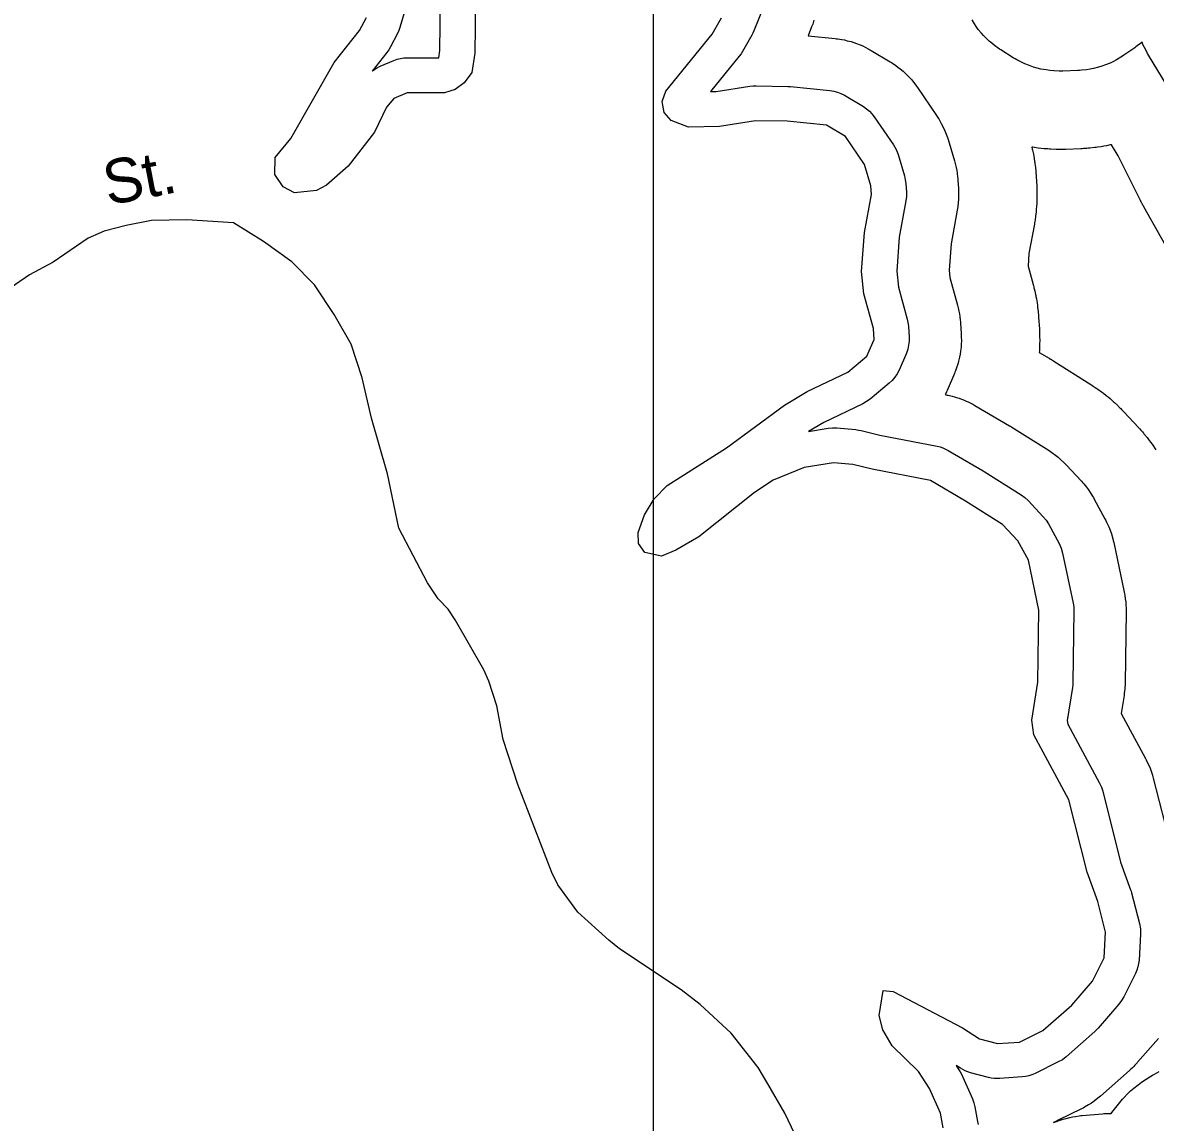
# Model space of a CAD drawing. Extents: x 1113032 to 1302912, y 664689 to 832535.
# Drawn here: x 1146316 to 1148745, y 741476 to 743835 of the extents above; entities that cross this region are included whole.
import ezdxf

# ---------------------------------------------------------------- set-up
doc = ezdxf.new("R2010")
doc.units = 0
for name, color, linetype in [('Exist Hydrographic Buffer Line', 7, 'Continuous'), ('Exist Hydrographic Lake Shore', 7, 'Continuous'), ('Exist Road Non-System Type 51', 7, 'Continuous'), ('Exist Road Non-System Type 51 Label', 7, 'Continuous'), ('Map Preparation Inset Cut Line', 7, 'Continuous')]:
    doc.layers.add(name, color=color, linetype=linetype)

msp = doc.modelspace()

# ---------------------------------------------------------------- linework, layer by layer
at = {"layer": 'Exist Hydrographic Buffer Line'}
for points in [[(1147136.6, 743863.2), (1147125.1, 743824.9), (1147122.8, 743818.4), (1147119.9, 743812), (1147105.2, 743783.7), (1147101.5, 743777.3), (1147097.2, 743771.3), (1147065.3, 743731.4), (1147067, 743732.8), (1147074.6, 743737.8), (1147082.7, 743741.8), (1147111.8, 743754), (1147118.9, 743756.6), (1147126.2, 743758.4), (1147133.7, 743759.5), (1147141.2, 743759.9), (1147208.4, 743759.6), (1147210.9, 743775.8), (1147212.4, 743886.1)], [(1147903.8, 743867.1), (1147884.3, 743817.8), (1147882.2, 743812.9), (1147879.7, 743808.2), (1147859.9, 743773.4), (1147856.6, 743768.1), (1147852.8, 743763.1), (1147791, 743687.3), (1147803.5, 743687.5), (1147875.8, 743699), (1147882.4, 743699.7), (1147889, 743699.9), (1147957, 743698.6), (1147959.9, 743698.5), (1147962.9, 743698.2), (1148047.1, 743689.8), (1148055.3, 743688.5), (1148063.2, 743686.4), (1148070.9, 743683.4), (1148078.2, 743679.5), (1148118.9, 743655.2), (1148125.6, 743650.7), (1148131.8, 743645.4), (1148137.4, 743639.6), (1148142.3, 743633.1), (1148183.3, 743573), (1148189.1, 743563.1), (1148193.2, 743552.3), (1148206.9, 743506.6), (1148208.9, 743498.4), (1148209.9, 743490.1), (1148211.2, 743471.9), (1148211.2, 743462.6), (1148210.1, 743453.3), (1148195.9, 743375.4), (1148190.4, 743302.4), (1148194.2, 743267.5), (1148212.9, 743199.4), (1148214.5, 743192), (1148215.4, 743184.4), (1148216.9, 743160.6), (1148217, 743151.8), (1148216, 743143.1), (1148214, 743134.6), (1148211.1, 743126.3), (1148195.6, 743090.1), (1148191.6, 743082.1), (1148186.7, 743074.6), (1148180.9, 743067.8), (1148174.4, 743061.7), (1148133.3, 743027.7), (1148125.9, 743022.3), (1148117.9, 743017.8), (1148034.2, 742977.8), (1148001.6, 742958.4), (1148043.3, 742965.1), (1148052.5, 742966), (1148061.9, 742965.8), (1148103, 742962.2), (1148108.6, 742961.4), (1148114.2, 742960.3), (1148154.2, 742950.5), (1148277.3, 742926.6), (1148283.5, 742925.1), (1148289.5, 742923.1), (1148295.3, 742920.6), (1148300.9, 742917.6), (1148375.7, 742873.7), (1148376.7, 742873.1), (1148377.7, 742872.5), (1148457.2, 742822.4), (1148465.1, 742816.7), (1148472.1, 742810), (1148504.8, 742775), (1148510.7, 742767.7), (1148515.7, 742759.8), (1148538.6, 742717.7), (1148543.1, 742707.8), (1148546.1, 742697.3), (1148568.7, 742590.3), (1148569.9, 742582.1), (1148570.3, 742573.8), (1148568.2, 742419.8), (1148568, 742414.5), (1148567.3, 742409.2), (1148556.3, 742338), (1148557.2, 742330.7), (1148625.4, 742203.7), (1148629.3, 742195.4), (1148632.1, 742186.6), (1148670.6, 742034.6), (1148692.1, 741975.1), (1148693.1, 741971.9), (1148694.1, 741968.6), (1148711.1, 741903.1), (1148713.2, 741891.5), (1148713.4, 741879.7), (1148710, 741824.2), (1148709.2, 741816.8), (1148707.6, 741809.5), (1148705.3, 741802.3), (1148702.3, 741795.5), (1148677.6, 741745.6), (1148672.8, 741737.3), (1148667, 741729.7), (1148622.5, 741678.5), (1148619.2, 741674.8), (1148615.6, 741671.4), (1148553.5, 741616.7), (1148545.7, 741610.6), (1148537, 741605.7), (1148487.1, 741581), (1148480.4, 741578.1), (1148473.5, 741575.9), (1148466.4, 741574.4), (1148459.2, 741573.5), (1148411.6, 741570.2), (1148405.5, 741570), (1148399.3, 741570.3), (1148393.2, 741571.2), (1148387.2, 741572.5), (1148348.7, 741582.7), (1148337.5, 741586.6), (1148327.2, 741592.2), (1148318.1, 741598), (1148323.8, 741589.1), (1148326.6, 741584.4), (1148329.1, 741579.4), (1148352.8, 741526.9), (1148356, 741518.4), (1148358.2, 741509.6), (1148363.9, 741478.3), (1148364.8, 741471.4)], [(1148012.9, 743840.5), (1148010.2, 743832.2), (1148009.1, 743829.1), (1148007.9, 743826), (1148000.4, 743807), (1148058.2, 743801.3), (1148061.3, 743800.9), (1148064.3, 743800.5), (1148072.5, 743799.2), (1148078.5, 743798.1), (1148084.5, 743796.6), (1148092.5, 743794.5), (1148098.4, 743792.7), (1148104.2, 743790.6), (1148111.8, 743787.6), (1148117.5, 743785.2), (1148123, 743782.5), (1148130.3, 743778.7), (1148133, 743777.2), (1148135.7, 743775.7), (1148176.4, 743751.3), (1148178.9, 743749.7), (1148181.5, 743748.1), (1148188.2, 743743.5), (1148193.1, 743740), (1148197.9, 743736.2), (1148204.1, 743731), (1148208.6, 743727), (1148212.9, 743722.7), (1148218.5, 743716.8), (1148222.5, 743712.3), (1148226.3, 743707.6), (1148231.3, 743701.2), (1148233.1, 743698.7), (1148234.8, 743696.3), (1148275.8, 743636.2), (1148278.2, 743632.6), (1148280.4, 743628.9), (1148286.1, 743618.9), (1148290.1, 743611.3), (1148293.5, 743603.4), (1148297.7, 743592.7), (1148299.1, 743588.6), (1148300.5, 743584.6), (1148314.2, 743538.8), (1148315.1, 743535.8), (1148315.8, 743532.8), (1148317.8, 743524.6), (1148319.1, 743518.4), (1148320, 743512.2), (1148321.1, 743503.9), (1148321.4, 743500.8), (1148321.7, 743497.6), (1148322.9, 743479.4), (1148323.1, 743476), (1148323.2, 743472.5), (1148323.2, 743463.2), (1148323, 743456.2), (1148322.4, 743449.3), (1148321.3, 743440.1), (1148320.9, 743436.6), (1148320.3, 743433.2), (1148307.1, 743361.1), (1148302.9, 743304.3), (1148304.6, 743288.5), (1148320.9, 743229), (1148321.6, 743226.3), (1148322.2, 743223.5), (1148323.9, 743216.1), (1148325, 743210.5), (1148325.8, 743204.8), (1148326.6, 743197.3), (1148326.9, 743194.4), (1148327.2, 743191.6), (1148328.7, 743167.8), (1148328.9, 743164.6), (1148328.9, 743161.3), (1148329, 743152.5), (1148328.8, 743145.9), (1148328.3, 743139.4), (1148327.3, 743130.7), (1148326.4, 743124.2), (1148325.1, 743117.8), (1148323.1, 743109.2), (1148321.5, 743102.9), (1148319.4, 743096.7), (1148316.4, 743088.4), (1148315.3, 743085.3), (1148314, 743082.3), (1148298.6, 743046.1), (1148297.2, 743043), (1148295.8, 743040), (1148294.4, 743037.3), (1148298.7, 743036.5), (1148301, 743036), (1148303.3, 743035.5), (1148309.5, 743034), (1148314.1, 743032.8), (1148318.6, 743031.4), (1148324.6, 743029.4), (1148329.1, 743027.9), (1148333.5, 743026.1), (1148339.3, 743023.6), (1148343.7, 743021.6), (1148347.9, 743019.5), (1148353.5, 743016.5), (1148355.6, 743015.4), (1148357.6, 743014.2), (1148432.4, 742970.3), (1148432.8, 742970.1), (1148433.1, 742969.9), (1148434.1, 742969.3), (1148434.9, 742968.8), (1148435.6, 742968.4), (1148436.7, 742967.7), (1148437, 742967.5), (1148437.4, 742967.3), (1148517, 742917.1), (1148520, 742915.2), (1148523, 742913.1), (1148530.8, 742907.4), (1148536.5, 742903), (1148542, 742898.2), (1148549, 742891.5), (1148551.6, 742889), (1148554.1, 742886.4), (1148586.7, 742851.4), (1148589.1, 742848.7), (1148591.4, 742846.1), (1148597.3, 742838.8), (1148601.6, 742833.2), (1148605.6, 742827.3), (1148610.6, 742819.3), (1148612.4, 742816.3), (1148614.1, 742813.3), (1148637, 742771.2), (1148638.9, 742767.6), (1148640.6, 742764), (1148645.1, 742754), (1148648.2, 742746.5), (1148650.7, 742738.8), (1148653.7, 742728.3), (1148654.8, 742724.4), (1148655.7, 742720.4), (1148678.3, 742613.3), (1148678.9, 742610.3), (1148679.4, 742607.3), (1148680.6, 742599.1), (1148681.4, 742592.9), (1148681.8, 742586.8), (1148682.2, 742578.5), (1148682.3, 742575.4), (1148682.3, 742572.3), (1148680.2, 742418.3), (1148680.2, 742416.3), (1148680.1, 742414.3), (1148679.8, 742409), (1148679.6, 742405.1), (1148679.2, 742401.1), (1148678.5, 742395.9), (1148678.3, 742393.9), (1148678, 742392), (1148672, 742353.6), (1148724.1, 742256.7), (1148725.7, 742253.7), (1148727.1, 742250.6), (1148731, 742242.2), (1148733.7, 742235.9), (1148735.9, 742229.5), (1148738.7, 742220.8), (1148739.7, 742217.5), (1148740.6, 742214.2), (1148777.9, 742067.4)], [(1148812.6, 743630.7), (1148730.3, 743765.7), (1148728.4, 743769), (1148726.5, 743772.4), (1148721.7, 743781.7), (1148718.4, 743788.7), (1148716.5, 743793.4), (1148713.4, 743790.8), (1148706.2, 743785.2), (1148703.5, 743783.1), (1148700.7, 743781.1), (1148677.7, 743765.3), (1148674.4, 743763.1), (1148671, 743761.1), (1148661.9, 743755.7), (1148655, 743751.9), (1148647.8, 743748.7), (1148638, 743744.7), (1148630.5, 743741.9), (1148623, 743739.7), (1148612.7, 743737.1), (1148605, 743735.4), (1148597.1, 743734.3), (1148586.6, 743733.1), (1148582.7, 743732.8), (1148578.7, 743732.6), (1148547, 743731.4), (1148542.8, 743731.3), (1148538.7, 743731.4), (1148527.4, 743731.8), (1148519.1, 743732.4), (1148510.8, 743733.7), (1148499.8, 743735.8), (1148491.6, 743737.6), (1148483.6, 743740.1), (1148473, 743743.8), (1148465.2, 743746.9), (1148457.7, 743750.5), (1148447.7, 743755.8), (1148444.1, 743757.8), (1148440.5, 743760), (1148413.9, 743776.7), (1148410.9, 743778.7), (1148407.9, 743780.8), (1148399.9, 743786.5), (1148394.2, 743791), (1148388.7, 743795.9), (1148381.6, 743802.6), (1148376.4, 743807.8), (1148371.6, 743813.3), (1148365.4, 743820.9), (1148361, 743826.7), (1148357, 743832.8), (1148351.9, 743841.2)], [(1148795.8, 743305.7), (1148720.5, 743439.9), (1148720.4, 743440.1), (1148720.3, 743440.3), (1148720, 743440.9), (1148719.7, 743441.3), (1148719.5, 743441.8), (1148719.2, 743442.4), (1148719, 743442.6), (1148718.9, 743442.8), (1148718.1, 743444.4), (1148717.8, 743444.8), (1148717.6, 743445.3), (1148716.9, 743446.4), (1148716.5, 743447.3), (1148716, 743448.2), (1148715.4, 743449.4), (1148715.2, 743449.9), (1148714.9, 743450.3), (1148714.1, 743451.9), (1148714, 743452.1), (1148713.9, 743452.4), (1148713.6, 743452.9), (1148713.3, 743453.4), (1148713.1, 743453.8), (1148712.8, 743454.4), (1148712.7, 743454.7), (1148712.6, 743454.9), (1148665.4, 743549.3), (1148650.7, 743573.4), (1148648.3, 743572.9), (1148640.6, 743571.2), (1148634.8, 743570.1), (1148628.9, 743569.1), (1148621.1, 743568), (1148618.2, 743567.6), (1148615.2, 743567.2), (1148604.7, 743566.1), (1148603.2, 743565.9), (1148601.7, 743565.8), (1148597.8, 743565.5), (1148594.8, 743565.2), (1148591.9, 743565), (1148587.9, 743564.8), (1148586.4, 743564.7), (1148585, 743564.7), (1148553.3, 743563.5), (1148551.7, 743563.4), (1148550.1, 743563.4), (1148546, 743563.3), (1148542.8, 743563.3), (1148539.7, 743563.3), (1148535.5, 743563.4), (1148533.9, 743563.4), (1148532.3, 743563.5), (1148521.1, 743563.9), (1148518, 743564.1), (1148514.8, 743564.3), (1148506.5, 743564.9), (1148500.2, 743565.5), (1148494, 743566.3), (1148485.7, 743567.6), (1148482.6, 743568.1), (1148480, 743568.5), (1148481.2, 743563.8), (1148481.7, 743561.5), (1148482.2, 743559.2), (1148483.5, 743553.1), (1148484.4, 743548.5), (1148485.2, 743543.8), (1148486.1, 743537.6), (1148486.5, 743535.3), (1148486.8, 743532.9), (1148487.8, 743524.6), (1148487.9, 743523.4), (1148488.1, 743522.3), (1148488.4, 743519.1), (1148488.7, 743516.8), (1148488.9, 743514.4), (1148489.1, 743511.3), (1148489.2, 743510.1), (1148489.3, 743509), (1148490.5, 743490.8), (1148490.6, 743489.5), (1148490.7, 743488.2), (1148490.9, 743484.7), (1148491, 743482.1), (1148491.1, 743479.5), (1148491.1, 743476), (1148491.2, 743474.7), (1148491.2, 743473.4), (1148491.2, 743464.1), (1148491.2, 743461.5), (1148491.2, 743458.9), (1148491, 743451.9), (1148490.8, 743446.7), (1148490.4, 743441.5), (1148489.8, 743434.6), (1148489.5, 743432), (1148489.2, 743429.4), (1148488.1, 743420.2), (1148488, 743418.9), (1148487.8, 743417.6), (1148487.4, 743414.1), (1148487, 743411.5), (1148486.6, 743409), (1148486, 743405.5), (1148485.8, 743404.3), (1148485.6, 743403), (1148474, 743339.7), (1148472, 743313.2), (1148482.9, 743273.5), (1148483.2, 743272.5), (1148483.4, 743271.4), (1148484.2, 743268.7), (1148484.7, 743266.6), (1148485.2, 743264.5), (1148485.8, 743261.8), (1148486.1, 743260.7), (1148486.3, 743259.7), (1148487.9, 743252.2), (1148488.4, 743250.2), (1148488.8, 743248.1), (1148489.9, 743242.5), (1148490.7, 743238.3), (1148491.3, 743234.1), (1148492.1, 743228.4), (1148492.4, 743226.3), (1148492.6, 743224.2), (1148493.5, 743216.6), (1148493.6, 743215.6), (1148493.8, 743214.5), (1148494, 743211.7), (1148494.3, 743209.5), (1148494.4, 743207.4), (1148494.7, 743204.6), (1148494.7, 743203.5), (1148494.8, 743202.4), (1148496.3, 743178.7), (1148496.4, 743177.4), (1148496.5, 743176.2), (1148496.6, 743172.9), (1148496.8, 743170.5), (1148496.8, 743168), (1148496.9, 743164.7), (1148496.9, 743163.5), (1148496.9, 743162.3), (1148497, 743153.5), (1148497, 743151.1), (1148496.9, 743148.6), (1148496.8, 743142), (1148496.6, 743137.1), (1148496.3, 743132.2), (1148495.9, 743127.8), (1148517.4, 743115.2), (1148517.6, 743115.1), (1148517.7, 743115), (1148518.1, 743114.8), (1148518.4, 743114.6), (1148518.7, 743114.5), (1148519, 743114.3), (1148519.2, 743114.2), (1148519.3, 743114.1), (1148520.3, 743113.5), (1148520.6, 743113.3), (1148520.9, 743113.1), (1148521.7, 743112.7), (1148522.2, 743112.3), (1148522.8, 743112), (1148523.5, 743111.5), (1148523.8, 743111.4), (1148524.1, 743111.2), (1148525.1, 743110.6), (1148525.2, 743110.5), (1148525.4, 743110.4), (1148525.8, 743110.2), (1148526, 743110), (1148526.3, 743109.8), (1148526.7, 743109.6), (1148526.8, 743109.5), (1148527, 743109.4), (1148606.5, 743059.3), (1148607.7, 743058.5), (1148608.8, 743057.8), (1148611.8, 743055.8), (1148614.1, 743054.3), (1148616.3, 743052.8), (1148619.3, 743050.7), (1148620.4, 743049.9), (1148621.5, 743049.1), (1148629.4, 743043.4), (1148631.6, 743041.8), (1148633.7, 743040.2), (1148639.4, 743035.7), (1148643.7, 743032.3), (1148647.8, 743028.8), (1148653.2, 743024), (1148655.3, 743022.2), (1148657.2, 743020.4), (1148664.3, 743013.7), (1148665.3, 743012.8), (1148666.3, 743011.8), (1148668.9, 743009.3), (1148670.8, 743007.4), (1148672.7, 743005.4), (1148675.2, 743002.8), (1148676.1, 743001.8), (1148677.1, 743000.9), (1148709.7, 742965.8), (1148710.6, 742964.9), (1148711.5, 742963.9), (1148713.8, 742961.3), (1148715.6, 742959.3), (1148717.3, 742957.3), (1148719.6, 742954.6), (1148720.4, 742953.6), (1148721.3, 742952.6), (1148727.2, 742945.3), (1148728.9, 742943.2), (1148730.5, 742941.2), (1148734.8, 742935.6), (1148738, 742931.3), (1148741, 742927), (1148744.9, 742921.2), (1148746.4, 742918.9)], [(1148751.6, 741656.2), (1148707.1, 741605), (1148705.9, 741603.6), (1148704.6, 741602.3), (1148701.2, 741598.6), (1148698.7, 741596), (1148696, 741593.4), (1148692.4, 741590), (1148691, 741588.7), (1148689.7, 741587.5), (1148627.6, 741532.7), (1148624.8, 741530.3), (1148621.9, 741528), (1148614, 741521.9), (1148608, 741517.6), (1148601.7, 741513.7), (1148593.1, 741508.7), (1148589.9, 741506.9), (1148586.6, 741505.2), (1148536.6, 741480.6), (1148534.2, 741479.4), (1148531.7, 741478.3), (1148526.9, 741476.2), (1148547.5, 741482.8), (1148550.5, 741483.7), (1148553.5, 741484.5), (1148561.5, 741486.6), (1148567.6, 741488), (1148573.7, 741489), (1148581.9, 741490.2), (1148585, 741490.6), (1148588.1, 741490.9), (1148631.6, 741494.7), (1148634.6, 741495), (1148637.6, 741495.1), (1148645.6, 741495.4), (1148650.3, 741495.4), (1148651.8, 741497.5), (1148671.6, 741522.3), (1148674.5, 741525.7), (1148677.4, 741529), (1148685.6, 741537.7), (1148691.9, 741543.9), (1148698.7, 741549.6), (1148708.1, 741556.9), (1148711.6, 741559.6), (1148715.3, 741562.1), (1148735.4, 741575.3), (1148739.1, 741577.6), (1148742.9, 741579.7), (1148753.1, 741585.4)]]:
    msp.add_lwpolyline(points, dxfattribs=at)
at = {"layer": 'Exist Hydrographic Lake Shore'}
for points in [[(1147287.4, 743885.1), (1147285.8, 743769.6), (1147279.5, 743728.6), (1147263.1, 743706), (1147243.7, 743692.1), (1147221, 743684.6), (1147140.9, 743684.9), (1147111.8, 743672.6), (1147096.6, 743654.2), (1147070.4, 743600), (1147014.4, 743527.6), (1146967.5, 743486.7), (1146946.4, 743475.3), (1146899.3, 743469.9), (1146874.7, 743482.8), (1146857.2, 743509.2), (1146857.5, 743546.1), (1146891.4, 743587.1), (1146984, 743749.8), (1147038.6, 743818.1), (1147053.3, 743846.5)], [(1148160.8, 741674.9), (1148152.6, 741705.7), (1148161.4, 741758.9), (1148183, 741756.6), (1148331.2, 741678.8), (1148367.8, 741655.2), (1148406.4, 741645), (1148454, 741648.3), (1148503.9, 741672.9), (1148565.9, 741727.7), (1148610.4, 741778.9), (1148635.1, 741828.8), (1148638.5, 741884.2), (1148621.5, 741949.7), (1148598.8, 742012.6), (1148559.4, 742168.2), (1148484.5, 742307.5), (1148480.5, 742339.1), (1148493.2, 742420.7), (1148495.3, 742574.8), (1148472.7, 742681.9), (1148449.9, 742723.9), (1148417.3, 742758.9), (1148337.7, 742809.1), (1148263, 742852.9), (1148138.1, 742877.2), (1148096.4, 742887.4), (1148055.2, 742891.1), (1147992.1, 742880.9), (1147925.5, 742854.1), (1147885.4, 742827.7), (1147766.2, 742731.9), (1147717.1, 742703.7), (1147685.8, 742691.1), (1147650.3, 742698.5), (1147636.6, 742717.9), (1147635.7, 742741.6), (1147649.3, 742779.5), (1147670.4, 742813.5), (1147698.1, 742842.2), (1147825.6, 742923.1), (1147949.8, 743014.9), (1147998.7, 743044), (1148085.5, 743085.5), (1148126.6, 743119.5), (1148142.1, 743155.8), (1148140.5, 743179.5), (1148120.2, 743253.5), (1148115.1, 743301.2), (1148121.4, 743385), (1148136.3, 743466.8), (1148135.1, 743485), (1148121.4, 743530.7), (1148080.4, 743590.8), (1148039.7, 743615.2), (1147955.5, 743623.6), (1147887.5, 743624.9), (1147810.2, 743612.7), (1147744.1, 743611.3), (1147707, 743625.4), (1147692, 743642.4), (1147687.5, 743665.8), (1147695, 743688.2), (1147794.7, 743810.5), (1147814.5, 743845.3)], [(1148290.1, 741464.7), (1148284.4, 741496.1), (1148260.7, 741548.6), (1148237.3, 741585.1), (1148180.8, 741640.4), (1148160.8, 741674.9)]]:
    msp.add_lwpolyline(points, dxfattribs=at)
at = {"layer": 'Exist Road Non-System Type 51'}
msp.add_lwpolyline([(1148016.5, 741358), (1147950.4, 741495.9), (1147914.2, 741559), (1147893.3, 741593.5), (1147835.3, 741667.2), (1147768.9, 741729.3), (1147727.9, 741760.3), (1147596.1, 741848.3), (1147572.8, 741866.8), (1147506.4, 741926.9), (1147463.9, 741985.8), (1147450.6, 742012.4), (1147377.9, 742200.6), (1147346.7, 742297.4), (1147332.7, 742369.9), (1147316.1, 742422.4), (1147304.7, 742446.9), (1147243.9, 742554.5), (1147228.6, 742577.1), (1147207, 742599.5), (1147183.9, 742633.9), (1147122.7, 742750.6), (1147098.2, 742867.6), (1147063.8, 742986.8), (1147044.2, 743073.1), (1147020.4, 743145.8), (1146984.2, 743209.2), (1146942.2, 743272.5), (1146893.6, 743322), (1146832.8, 743365.6), (1146767.9, 743405.6), (1146667.9, 743412.5), (1146592.1, 743410.8), (1146537.7, 743400.4), (1146491.2, 743387.8), (1146456.7, 743372.8), (1146381.2, 743321.1), (1146330.5, 743294.5), (1146207.6, 743210)], dxfattribs=at)
at = {"layer": 'Map Preparation Inset Cut Line'}
msp.add_lwpolyline([(1223351.7, 748878.2), (1147668.5, 748878.2), (1147668.5, 704629.7), (1208143, 704629.7), (1208143, 720169.6), (1223351.7, 720169.6)], close=True, dxfattribs=at)

# ---------------------------------------------------------------- texts
at = {"layer": 'Exist Road Non-System Type 51 Label'}
msp.add_text('St.', height=95, rotation=10.8304, dxfattribs=at).set_placement((1146498.9, 743443))

doc.saveas('drawing.dxf')
